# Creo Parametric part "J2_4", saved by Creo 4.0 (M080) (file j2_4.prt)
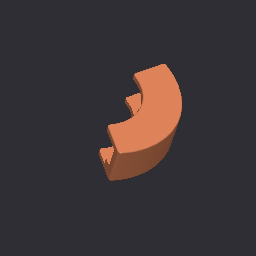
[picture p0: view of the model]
Units: Inch lbm Second (Pro/E Default); INCH, POUND, SECS

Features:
  1. datum plane "DTM1"
  2. datum plane "DTM2"
  3. datum plane "DTM3"
  4. datum axis
  5. protrusion
  6. round
  7. datum plane "DTM7"
  8. cut
  9. pattern
  10. protrusion
  11. protrusion
  12. round
  13. round
  14. datum plane "DTM5"
  15. protrusion
  16. datum plane "DTM6"
  17. cut

Other named items: WHEEL_AXIS

Layers: BASE_DAT

Surfaces: 17 cylinder, 14 torus, 10 plane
